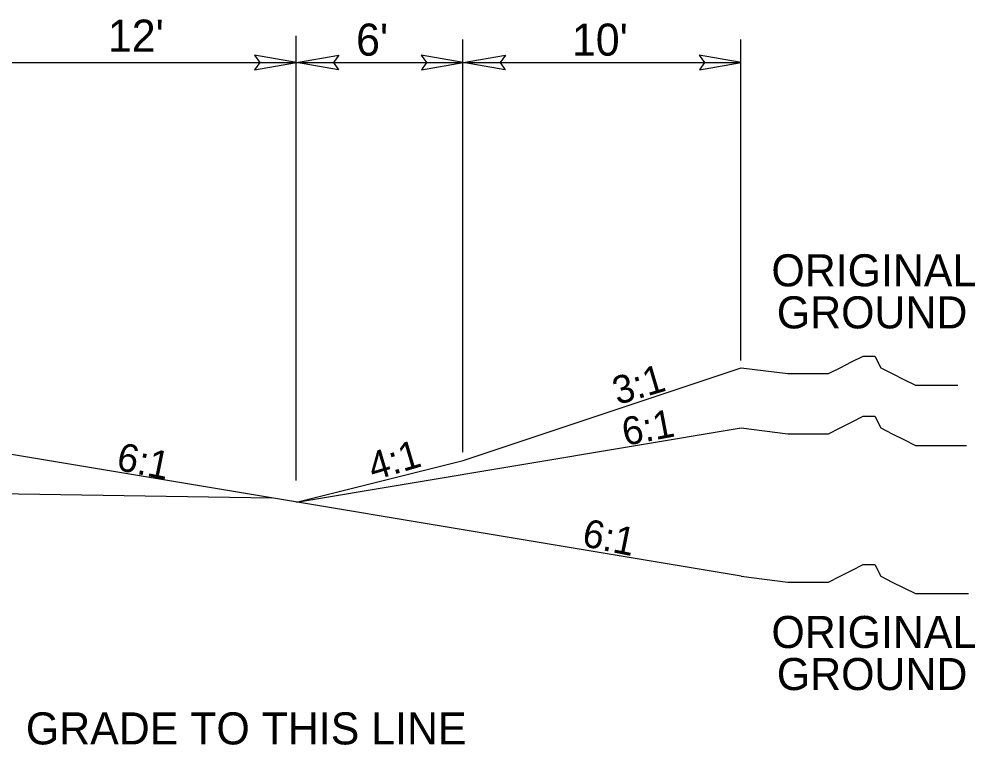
# Model space of a CAD drawing. Extents: x 2176156 to 2177167, y 76401 to 76644.
# Drawn here: x 2177132.18 to 2177166.57, y 76504.21 to 76530.31 of the extents above; entities that cross this region are included whole.
import ezdxf

# ---------------------------------------------------------------- set-up
doc = ezdxf.new("R2010")
doc.units = 0
for name, color, linetype in [('Exist Building', 7, 'Continuous'), ('Exist Roads Curbs', 7, 'Continuous'), ('Exist Roads EOP Other', 7, 'Continuous'), ('Exist Roads Soil', 7, 'Continuous'), ('Exist Structure Minor Culvert Topo', 7, 'Continuous'), ('Old_Level_1', 7, 'Continuous'), ('Old_Level_3', 7, 'Continuous')]:
    doc.layers.add(name, color=color, linetype=linetype)

msp = doc.modelspace()

# ---------------------------------------------------------------- linework, layer by layer
at = {"layer": 'Exist Building'}
msp.add_line((2177141.279, 76513.086), (2177115.083, 76513.476), dxfattribs=at)
at = {"layer": 'Exist Roads Curbs'}
for points in [[(2177158.163, 76517.772), (2177159.834, 76517.564), (2177160.252, 76517.564), (2177160.879, 76517.564), (2177161.297, 76517.564), (2177161.714, 76517.772), (2177162.132, 76517.982), (2177162.55, 76518.191), (2177162.967, 76518.191), (2177163.177, 76517.772), (2177163.595, 76517.564), (2177164.012, 76517.354), (2177164.43, 76517.146), (2177164.848, 76517.146), (2177165.265, 76517.146), (2177165.683, 76517.146), (2177165.954, 76517.146)], [(2177158.164, 76515.605), (2177159.834, 76515.397), (2177160.252, 76515.397), (2177160.879, 76515.397), (2177161.297, 76515.397), (2177161.715, 76515.605), (2177162.132, 76515.815), (2177162.55, 76516.025), (2177162.968, 76516.025), (2177163.177, 76515.605), (2177163.595, 76515.397), (2177164.013, 76515.188), (2177164.43, 76514.98), (2177164.848, 76514.98), (2177165.266, 76514.98), (2177165.683, 76514.98), (2177166.101, 76514.98), (2177166.264, 76514.98)], [(2177158.163, 76510.272), (2177159.834, 76510.064), (2177160.252, 76510.064), (2177160.879, 76510.064), (2177161.297, 76510.064), (2177161.714, 76510.272), (2177162.132, 76510.482), (2177162.55, 76510.691), (2177162.967, 76510.691), (2177163.177, 76510.272), (2177163.595, 76510.064), (2177164.012, 76509.854), (2177164.43, 76509.646), (2177164.848, 76509.646), (2177165.265, 76509.646), (2177165.683, 76509.646), (2177166.101, 76509.646), (2177166.341, 76509.646)]]:
    msp.add_lwpolyline(points, dxfattribs=at)
at = {"layer": 'Exist Roads EOP Other'}
for p, q in [((2177148.163, 76514.439), (2177158.163, 76517.772)), ((2177142.163, 76512.939), (2177148.163, 76514.439))]:
    msp.add_line(p, q, dxfattribs=at)
at = {"layer": 'Exist Roads Soil'}
for p, q in [((2177142.163, 76512.939), (2177158.163, 76515.605)), ((2177158.163, 76510.272), (2177130.212, 76514.931))]:
    msp.add_line(p, q, dxfattribs=at)
at = {"layer": 'Old_Level_1'}
for points in [[(2177140.654, 76528.484), (2177142.163, 76528.744), (2177140.645, 76529.012), (2177140.838, 76528.744)], [(2177143.673, 76528.484), (2177142.163, 76528.744), (2177143.681, 76529.012), (2177143.489, 76528.744)], [(2177146.654, 76528.484), (2177148.163, 76528.744), (2177146.645, 76529.012), (2177146.838, 76528.744)], [(2177149.673, 76528.484), (2177148.163, 76528.744), (2177149.681, 76529.012), (2177149.489, 76528.744)], [(2177156.654, 76528.484), (2177158.163, 76528.744), (2177156.645, 76529.012), (2177156.838, 76528.744)]]:
    msp.add_lwpolyline(points, close=True, dxfattribs=at)
at = {"layer": 'Old_Level_3'}
for p, q in [((2177142.151, 76513.717), (2177142.151, 76529.71)), ((2177148.151, 76514.734), (2177148.151, 76529.576)), ((2177158.151, 76518.036), (2177158.151, 76529.576)), ((2177130.163, 76528.744), (2177142.163, 76528.744)), ((2177142.163, 76528.744), (2177148.163, 76528.744)), ((2177148.163, 76528.744), (2177158.163, 76528.744))]:
    msp.add_line(p, q, dxfattribs=at)

# ---------------------------------------------------------------- texts
at = {"layer": 'Exist Roads Curbs'}
for s, rotation, p in [('3:1', 16.4649, (2177153.71, 76516.427)), ('6:1', 10.8168, (2177153.977, 76514.958)), ('6:1', 348.5135, (2177135.645, 76514.107)), ('4:1', 16.4649, (2177144.92, 76513.706)), ('6:1', 348.5135, (2177152.395, 76511.366))]:
    msp.add_text(s, height=1.0064, rotation=rotation, dxfattribs=at).set_placement(p)
at = {"layer": 'Exist Structure Minor Culvert Topo'}
for s, height, p in [("12' ", 1.1533, (2177135.378, 76529.139)), ("6'", 1.1533, (2177144.306, 76528.996)), ("10'", 1.1533, (2177152.071, 76528.996)), ('ORIGINAL', 1.1533, (2177159.247, 76520.698)), ('GROUND', 1.1533, (2177159.441, 76519.186)), ('ORIGINAL', 1.1533, (2177159.247, 76507.69)), ('GROUND', 1.1533, (2177159.441, 76506.178)), ('GRADE TO THIS LINE', 1.15334, (2177132.426, 76504.223))]:
    msp.add_text(s, height=height, dxfattribs=at).set_placement(p)

doc.saveas('drawing.dxf')
